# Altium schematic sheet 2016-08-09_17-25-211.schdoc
size 313 x 127 mm; SheetNumber: 1; SheetTotal: 1
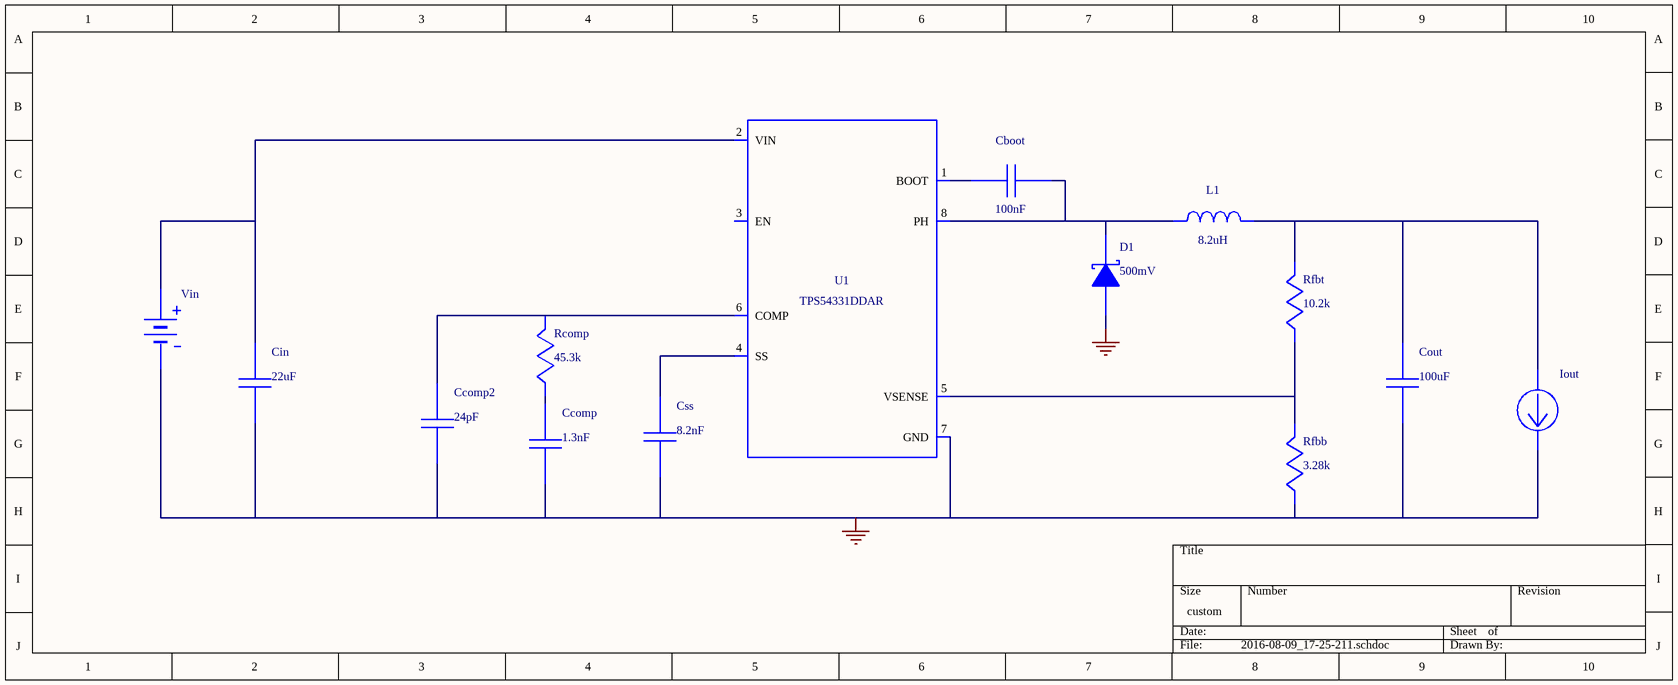
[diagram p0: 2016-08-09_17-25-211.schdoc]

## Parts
Cboot  value 100nF  (hidden comment: GRM155R61A104KA01D)
Ccomp  value 1.3nF  (hidden comment: GRM2165C2A132JA01D)
Ccomp2  value 24pF  (hidden comment: CL21C240JBANNNC)
Cin  value 22uF  (hidden comment: GRM32ER61E226KE15L)
Cout  value 100uF  (hidden comment: GRM31CR60J107ME39L)
Css  value 8.2nF  (hidden comment: GRM033R61A822KA01D)
D1  value 500mV  (hidden comment: B340A-13-F)
Iout  WB_CURRENT_LOAD  (value not drawn)
L1  value 8.2uH  (hidden comment: SRN8040-8R2Y)
Rcomp  value 45.3k  (hidden comment: CRCW040245K3FKED)
Rfbb  value 3.28k  (hidden comment: RT0805BRD073K28L)
Rfbt  value 10.2k  (hidden comment: CRCW040210K2FKED)
U1  TPS54331DDAR
Vin  WB_BATTERY  (value not drawn)

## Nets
0: Ccomp.2 Ccomp2.2 Cin.2 Cout.2 Css.2 D1.2(A) Iout.2(-) Rfbb.2 U1.7(GND) U1.9(ETPAD) Vin.2(-)
NetCboot_1: Cboot.1 U1.1(BOOT)
NetCboot_2: Cboot.2 D1.1(K) L1.2 U1.8(PH)
NetCcomp2_1: Ccomp2.1 Rcomp.1 U1.6(COMP)
NetCcomp_1: Ccomp.1 Rcomp.2
NetCin_1: Cin.1 U1.2(VIN) Vin.1(+)
NetCout_1: Cout.1 Iout.1(+) L1.1 Rfbt.1
NetCss_1: Css.1 U1.4(SS)
NetRfbb_1: Rfbb.1 Rfbt.2 U1.5(VSENSE)

Not connected (* = marked no-connect by the designer): U1 3(EN)

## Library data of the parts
Cboot = GRM155R61A104KA01D: GRM155R61A104KA0; Manufacturer Name: MuRata
Ccomp = GRM2165C2A132JA01D: GRM2165C2A132JA0; Manufacturer Name: MuRata
Ccomp2 = CL21C240JBANNNC: Manufacturer Name: Samsung Electro-Mechanics
Cin = GRM32ER61E226KE15L: GRM32ER61E226KE1; Manufacturer Name: MuRata
Cout = GRM31CR60J107ME39L: GRM31CR60J107ME3; Manufacturer Name: MuRata
Css = GRM033R61A822KA01D: GRM033R61A822KA0; Manufacturer Name: MuRata
D1 = B340A-13-F: Manufacturer Name: Diodes Inc.
L1 = SRN8040-8R2Y: Manufacturer Name: Bourns
Rcomp = CRCW040245K3FKED: Manufacturer Name: Vishay-Dale
Rfbb = RT0805BRD073K28L: Manufacturer Name: Yageo America
Rfbt = CRCW040210K2FKED: Manufacturer Name: Vishay-Dale
U1 = TPS54331DDAR: Manufacturer Name: Texas Instruments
